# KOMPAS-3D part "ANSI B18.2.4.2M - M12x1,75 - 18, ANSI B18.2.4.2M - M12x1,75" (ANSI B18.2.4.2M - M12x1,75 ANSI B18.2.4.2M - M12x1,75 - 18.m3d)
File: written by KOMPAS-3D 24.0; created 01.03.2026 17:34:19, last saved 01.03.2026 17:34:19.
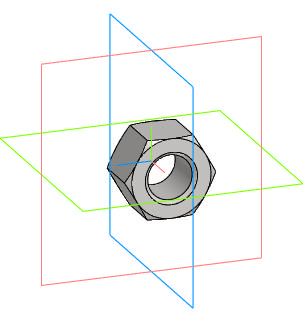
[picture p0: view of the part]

Document properties: Автор: R2D2; Полное имя файла: E:\Работа\Зайцев\GVWR3131M-2W-F-S Задвижка клиновая с выдвижным штоком DN.ru Ду50-200 Ру63\DN50\исходные материалы\ANSI B18.2.4.2M - M12x1,75 ANSI B18.2.4.2M - M12x1,75 - 18.m3d

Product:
- Body: Solid1  | qty 1
- Part/product: ANSI B18.2.4.2M - M12x1,75 - 18  | designation ANSI B18.2.4.2M - M12x1,75
    Комментарий: Типы метрических   шестигранных гаек   2
    additional columns: Сталь, мягкая

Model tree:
1. Solid1  (labels: Solid1)

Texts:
  ANSI B18.2.4.2M - M12x1,75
